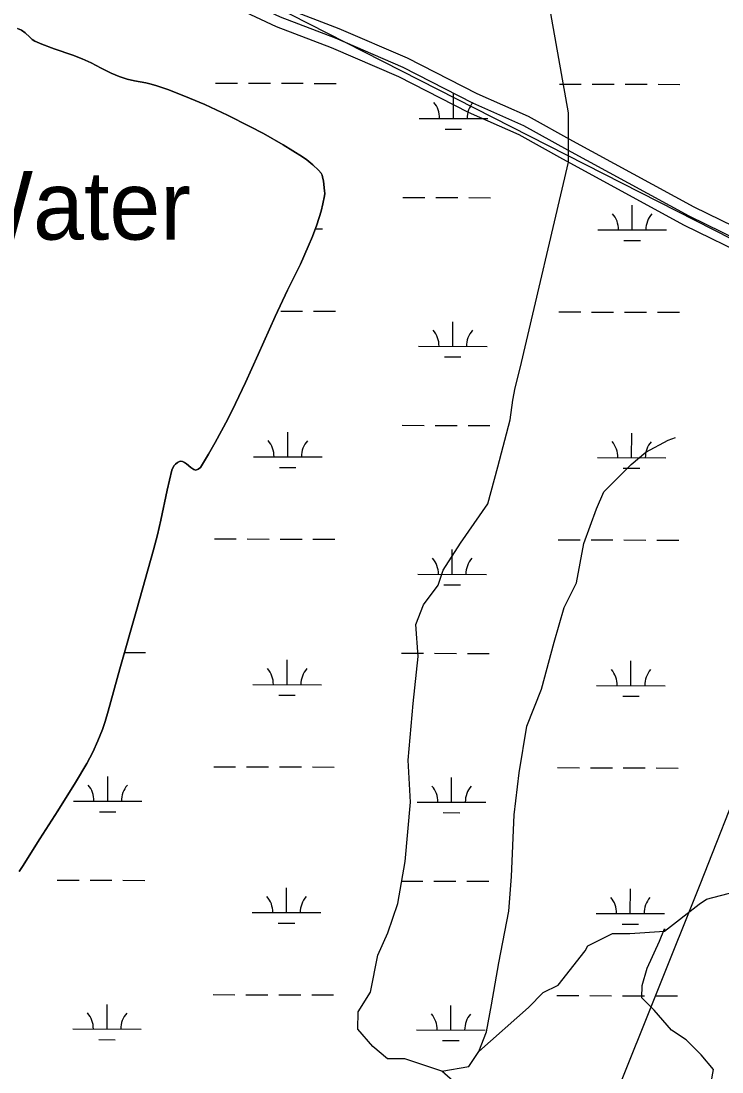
# Model space of a CAD drawing. Extents: x 3161615 to 3199515, y 867541 to 892976.
# Drawn here: x 3178916 to 3179939, y 876681 to 878215 of the extents above; entities that cross this region are included whole.
import ezdxf

# ---------------------------------------------------------------- set-up
doc = ezdxf.new("R2010")
doc.units = 0
for name, color, linetype in [('V-RIVR-IDEN', 7, 'Continuous'), ('V-ROAD-CNTR', 7, 'Continuous'), ('V-SITE-VEGE', 7, 'Continuous'), ('V-TOPO-BNDY', 7, 'Continuous'), ('V-TOPO-SHOR', 7, 'Continuous'), ('V-WETL-SWMP', 7, 'Continuous')]:
    doc.layers.add(name, color=color, linetype=linetype)

msp = doc.modelspace()

# ---------------------------------------------------------------- linework, layer by layer
at = {"layer": 'V-ROAD-CNTR'}
for points in [[(3180736.9, 877532.4), (3180600.2, 877601.6), (3180430.4, 877683.5), (3180339.3, 877732.1), (3180261.1, 877767.7), (3180178.8, 877806), (3180085.6, 877850.5), (3179995, 877895.6), (3179898, 877943.1), (3179721.1, 878039.2), (3179656.4, 878075.4), (3179581.6, 878108.4), (3179479.8, 878160.5), (3179380.1, 878203.6), (3179300.3, 878234), (3179180.9, 878290.4), (3179051.2, 878351.8), (3178954.2, 878389.2)], [(3180729.6, 877519.2), (3180593.6, 877588.2), (3180423.6, 877670.2), (3180332.7, 877718.6), (3180254.8, 877754.1), (3180172.4, 877792.4), (3180079.1, 877837), (3179988.4, 877882.2), (3179891.1, 877929.7), (3179713.9, 878026.1), (3179649.7, 878062), (3179575.1, 878094.9), (3179473.4, 878146.9), (3179374.5, 878189.7), (3179294.4, 878220.2), (3179174.5, 878276.9), (3179045.3, 878338), (3178948.8, 878375.2)], [(3180722.3, 877506.1), (3180587, 877574.7), (3180416.8, 877656.8), (3180326.1, 877705.2), (3180248.5, 877740.5), (3180166, 877778.8), (3180072.5, 877823.5), (3179981.7, 877868.7), (3179884.2, 877916.4), (3179706.6, 878012.9), (3179643, 878048.5), (3179568.7, 878081.4), (3179467, 878133.4), (3179368.8, 878175.8), (3179288.5, 878206.4), (3179168.1, 878263.3), (3179039.4, 878324.2), (3178943.4, 878361.2)]]:
    msp.add_lwpolyline(points, dxfattribs=at)
at = {"layer": 'V-SITE-VEGE'}
for p, q in [((3178910.6, 878203.8), (3178916.4, 878201.3)), ((3178916.4, 878201.3), (3178921.6, 878197.6)), ((3178921.6, 878197.6), (3178928.4, 878191)), ((3178928.4, 878191), (3178931.9, 878187.9)), ((3178931.9, 878187.9), (3178935.8, 878185.5)), ((3178935.8, 878185.5), (3178945.9, 878181.1)), ((3178945.9, 878181.1), (3178963.9, 878174.3)), ((3178963.9, 878174.3), (3178991.4, 878164.8)), ((3178991.4, 878164.8), (3179004.9, 878159.6)), ((3179004.9, 878159.6), (3179018.1, 878153.8)), ((3179018.1, 878153.8), (3179032.5, 878146.1)), ((3179032.5, 878146.1), (3179047.1, 878138.6)), ((3179047.1, 878138.6), (3179058.7, 878133.9)), ((3179058.7, 878133.9), (3179070.6, 878129.9)), ((3179070.6, 878129.9), (3179081.3, 878127.3)), ((3179081.3, 878127.3), (3179097.6, 878124.4)), ((3179097.6, 878124.4), (3179105.8, 878122.7)), ((3179105.8, 878122.7), (3179113.7, 878120.4)), ((3179113.7, 878120.4), (3179131.3, 878114.3)), ((3179131.3, 878114.3), (3179161.5, 878102.4)), ((3179161.5, 878102.4), (3179183.8, 878092.7)), ((3179183.8, 878092.7), (3179216.9, 878077.3)), ((3179216.9, 878077.3), (3179249.8, 878060.9)), ((3179249.8, 878060.9), (3179269.4, 878050.5)), ((3179269.4, 878050.5), (3179298.1, 878034.1)), ((3179298.1, 878034.1), (3179326.4, 878016.5)), ((3179326.4, 878016.5), (3179332.7, 878012.1)), ((3179332.7, 878012.1), (3179341.5, 878004.9)), ((3179341.5, 878004.9), (3179349.9, 877996.9)), ((3179349.9, 877996.9), (3179353.6, 877992.5)), ((3179353.6, 877992.5), (3179355, 877990)), ((3179355, 877990), (3179355.9, 877987.4)), ((3179355.9, 877987.4), (3179357.1, 877980.9)), ((3179357.1, 877980.9), (3179358.8, 877966.9)), ((3179358.8, 877966.9), (3179359, 877963.1)), ((3179358.7, 877959.4), (3179356.3, 877947.8)), ((3179359, 877963.1), (3179358.7, 877959.4)), ((3179353.6, 877937.1), (3179347.4, 877917.3)), ((3179356.3, 877947.8), (3179353.6, 877937.1)), ((3179347.4, 877917.3), (3179341.1, 877900.2)), ((3179341.1, 877900.2), (3179335, 877885.5)), ((3179335, 877885.5), (3179323.4, 877859.9)), ((3179323.4, 877859.9), (3179304.8, 877821.8)), ((3179304.8, 877821.8), (3179286.6, 877783.6)), ((3179286.6, 877783.6), (3179261.9, 877728.1)), ((3179261.9, 877728.1), (3179243.3, 877687)), ((3179243.3, 877687), (3179228.7, 877656.5)), ((3179228.7, 877656.5), (3179217.3, 877633.6)), ((3179217.3, 877633.6), (3179199.1, 877599.4)), ((3179199.1, 877599.4), (3179189.3, 877582.3)), ((3179189.3, 877582.3), (3179179.1, 877565.2)), ((3179139.2, 877565.8), (3179137.1, 877562.5)), ((3179141.1, 877567.9), (3179139.2, 877565.8)), ((3179143.8, 877570.1), (3179141.1, 877567.9)), ((3179146.8, 877571.6), (3179143.8, 877570.1)), ((3179148.8, 877572), (3179146.8, 877571.6)), ((3179151.2, 877571.9), (3179148.8, 877572)), ((3179154.4, 877570.5), (3179151.2, 877571.9)), ((3179157.4, 877568.3), (3179154.4, 877570.5)), ((3179163.5, 877563), (3179157.4, 877568.3)), ((3179179.1, 877565.2), (3179177.5, 877563.1)), ((3179135.7, 877558.9), (3179128.8, 877529.9)), ((3179137.1, 877562.5), (3179135.7, 877558.9)), ((3179167.8, 877560.1), (3179163.5, 877563)), ((3179169.3, 877559.4), (3179167.8, 877560.1)), ((3179170.9, 877559.2), (3179169.3, 877559.4)), ((3179174.4, 877560.5), (3179170.9, 877559.2)), ((3179177.5, 877563.1), (3179174.4, 877560.5)), ((3179128.8, 877529.9), (3179119.5, 877486.3)), ((3179119.5, 877486.3), (3179114.7, 877464.6)), ((3179114.7, 877464.6), (3179109.1, 877443)), ((3179109.1, 877443), (3179084.7, 877356)), ((3179084.7, 877356), (3179059.7, 877269)), ((3179059.7, 877269), (3179042.8, 877207.3)), ((3179042.8, 877207.3), (3179038.2, 877192)), ((3179038.2, 877192), (3179034.4, 877180.7)), ((3179034.4, 877180.7), (3179027.9, 877163.9)), ((3179027.9, 877163.9), (3179020.3, 877147.5)), ((3179020.3, 877147.5), (3179011.6, 877131.1)), ((3179011.6, 877131.1), (3178995.3, 877103)), ((3178995.3, 877103), (3178969.5, 877061.8)), ((3178969.5, 877061.8), (3178943.3, 877020.9)), ((3178943.3, 877020.9), (3178917.7, 876980.6)), ((3178917.7, 876980.6), (3178912.8, 876973.1))]:
    msp.add_line(p, q, dxfattribs=at)
at = {"layer": 'V-TOPO-BNDY'}
for p, q in [((3179906.8, 876954.4), (3180242.1, 877807.1)), ((3179703.3, 876445.8), (3179906.8, 876954.4))]:
    msp.add_line(p, q, dxfattribs=at)
at = {"layer": 'V-TOPO-SHOR'}
for points in [[(3179644.4, 877708.2), (3179714.6, 878008.9), (3179714.8, 878081), (3179686.4, 878239.6), (3179701, 878297.2), (3179672.3, 878369.4), (3179614.9, 878441.6), (3179542.9, 878470.7), (3179456.3, 878442.1), (3179355.4, 878413.5), (3179211.1, 878385.1), (3179110.3, 878399.8), (3179009.4, 878400.1), (3178908.5, 878429.2), (3178793.5, 878516), (3178750.3, 878530.5)], [(3178932.8, 878416.5), (3180491, 877623), (3180753.7, 877499.7)], [(3179004.9, 878159.6), (3178991.4, 878164.8), (3178963.9, 878174.3), (3178945.9, 878181.1), (3178935.8, 878185.5), (3178931.9, 878187.9), (3178928.4, 878191), (3178921.6, 878197.6), (3178916.4, 878201.3), (3178910.6, 878203.8)], [(3178912.8, 876973.1), (3178917.7, 876980.6), (3178943.3, 877020.9), (3178969.5, 877061.8), (3178995.3, 877103), (3179011.6, 877131.1), (3179020.3, 877147.5), (3179027.9, 877163.9), (3179034.4, 877180.7), (3179038.2, 877192), (3179042.8, 877207.3), (3179059.7, 877269), (3179084.7, 877356), (3179109.1, 877443), (3179114.7, 877464.6), (3179119.5, 877486.3), (3179128.8, 877529.9), (3179135.7, 877558.9), (3179137.1, 877562.5), (3179139.2, 877565.8), (3179141.1, 877567.9), (3179143.8, 877570.1), (3179146.8, 877571.6), (3179148.8, 877572), (3179151.2, 877571.9), (3179154.4, 877570.5), (3179157.4, 877568.3), (3179163.5, 877563), (3179167.8, 877560.1), (3179169.3, 877559.4), (3179170.9, 877559.2), (3179174.4, 877560.5), (3179177.5, 877563.1), (3179179.1, 877565.2), (3179189.3, 877582.3), (3179199.1, 877599.4), (3179217.3, 877633.6), (3179228.7, 877656.5), (3179243.3, 877687), (3179261.9, 877728.1), (3179286.6, 877783.6), (3179304.8, 877821.8), (3179323.4, 877859.9), (3179335, 877885.5), (3179341.1, 877900.2), (3179347.4, 877917.3), (3179353.6, 877937.1), (3179356.3, 877947.8), (3179358.7, 877959.4), (3179359, 877963.1), (3179358.8, 877966.9), (3179357.1, 877980.9), (3179355.9, 877987.4), (3179355, 877990), (3179353.6, 877992.5), (3179349.9, 877996.9), (3179341.5, 878004.9), (3179332.7, 878012.1), (3179326.4, 878016.5), (3179298.1, 878034.1), (3179269.4, 878050.5), (3179249.8, 878060.9), (3179216.9, 878077.3), (3179183.8, 878092.7), (3179161.5, 878102.4), (3179131.3, 878114.3), (3179113.7, 878120.4), (3179105.8, 878122.7), (3179097.6, 878124.4), (3179081.3, 878127.3), (3179070.6, 878129.9), (3179058.7, 878133.9), (3179047.1, 878138.6), (3179032.5, 878146.1), (3179018.1, 878153.8), (3179004.9, 878159.6)], [(3179558.6, 876656.2), (3179529.8, 876681.5), (3179475.8, 876699.6), (3179450.6, 876699.7), (3179429, 876717.8), (3179407.5, 876743.1), (3179407.6, 876768.3), (3179425.7, 876797.1), (3179436.6, 876851.1), (3179451.1, 876883.5), (3179465.7, 876926.7), (3179476.6, 876987.9), (3179484.1, 877074.4), (3179480.6, 877135.7), (3179488.1, 877218.5), (3179495.5, 877287), (3179492, 877333.8), (3179502.9, 877362.6), (3179524.6, 877391.4), (3179531.9, 877413), (3179557.2, 877452.6), (3179597, 877510.1), (3179611.6, 877564.1), (3179629.8, 877632.6), (3179633.5, 877661.4), (3179637.1, 877679.4), (3179644.4, 877708.2)], [(3179529.8, 876681.5), (3179569.5, 876688.6), (3179584, 876710.2), (3179594.9, 876739), (3179602.2, 876778.6), (3179613.2, 876839.8), (3179627.8, 876915.4), (3179631.5, 876965.9), (3179635.4, 877056), (3179642.8, 877117.2), (3179653.8, 877185.6), (3179675.5, 877239.6), (3179693.7, 877308.1), (3179708.3, 877358.5), (3179726.4, 877394.5), (3179737.4, 877452.1), (3179755.5, 877502.5), (3179766.4, 877527.7), (3179806.2, 877567.2), (3179827.8, 877585.2), (3179860.3, 877603.1), (3179871.1, 877606.7)], [(3179584, 876710.2), (3179656.2, 876774.8), (3179677.9, 876796.4), (3179699.6, 876807.1), (3179739.3, 876857.5), (3179743, 876864.7), (3179779.1, 876882.6), (3179804.3, 876882.5), (3179854.7, 876886), (3179905.3, 876925.5), (3179916.1, 876932.7), (3180024.3, 876961.2)], [(3179918.9, 876640.8), (3179926.3, 876684), (3179908.3, 876705.7), (3179886.7, 876727.3), (3179865.2, 876741.8), (3179840, 876770.7), (3179822, 876788.8), (3179822.1, 876806.8), (3179829.4, 876832), (3179847.5, 876871.6), (3179854.7, 876889.6), (3179854.7, 876886)]]:
    msp.add_lwpolyline(points, dxfattribs=at)
at = {"layer": 'V-WETL-SWMP'}
for p, q in [((3178916.4, 878201.3), (3178910.6, 878203.8)), ((3178921.6, 878197.6), (3178916.4, 878201.3)), ((3178928.4, 878191), (3178921.6, 878197.6)), ((3178931.9, 878187.9), (3178928.4, 878191)), ((3178935.8, 878185.5), (3178931.9, 878187.9)), ((3178945.9, 878181.1), (3178935.8, 878185.5)), ((3178963.9, 878174.3), (3178945.9, 878181.1)), ((3178991.4, 878164.8), (3178963.9, 878174.3)), ((3179004.9, 878159.6), (3178991.4, 878164.8)), ((3179018.1, 878153.8), (3179004.9, 878159.6)), ((3179032.5, 878146.1), (3179018.1, 878153.8)), ((3179047.1, 878138.6), (3179032.5, 878146.1)), ((3179058.7, 878133.9), (3179047.1, 878138.6)), ((3179070.6, 878129.9), (3179058.7, 878133.9)), ((3179081.3, 878127.3), (3179070.6, 878129.9)), ((3179097.6, 878124.4), (3179081.3, 878127.3)), ((3179105.8, 878122.7), (3179097.6, 878124.4)), ((3179113.7, 878120.4), (3179105.8, 878122.7)), ((3179131.3, 878114.3), (3179113.7, 878120.4)), ((3179199.6, 878124.2), (3179231.6, 878124.1)), ((3179247.6, 878124.1), (3179279.6, 878124)), ((3179295.6, 878123.9), (3179327.6, 878123.9)), ((3179343.6, 878123.8), (3179375.6, 878123.7)), ((3179701.5, 878122.8), (3179733.5, 878122.7)), ((3179749.5, 878122.7), (3179781.5, 878122.6)), ((3179797.5, 878122.6), (3179829.5, 878122.5)), ((3179845.5, 878122.4), (3179877.5, 878122.3)), ((3179161.5, 878102.4), (3179131.3, 878114.3)), ((3179183.8, 878092.7), (3179161.5, 878102.4)), ((3179546.8, 878072.5), (3179546.9, 878108.5)), ((3179216.9, 878077.3), (3179183.8, 878092.7)), ((3179249.8, 878060.9), (3179216.9, 878077.3)), ((3179496.8, 878072.7), (3179596.8, 878072.4)), ((3179269.4, 878050.5), (3179249.8, 878060.9)), ((3179534.7, 878057.1), (3179558.7, 878057)), ((3179298.1, 878034.1), (3179269.4, 878050.5)), ((3179326.4, 878016.5), (3179298.1, 878034.1)), ((3179332.7, 878012.1), (3179326.4, 878016.5)), ((3179341.5, 878004.9), (3179332.7, 878012.1)), ((3179349.9, 877996.9), (3179341.5, 878004.9)), ((3179353.6, 877992.5), (3179349.9, 877996.9)), ((3179355, 877990), (3179353.6, 877992.5)), ((3179355.9, 877987.4), (3179355, 877990)), ((3179357.1, 877980.9), (3179355.9, 877987.4)), ((3179358.8, 877966.9), (3179357.1, 877980.9)), ((3179359, 877963.1), (3179358.8, 877966.9)), ((3179356.3, 877947.8), (3179358.7, 877959.4)), ((3179358.7, 877959.4), (3179359, 877963.1)), ((3179473.1, 877957.3), (3179505.1, 877957.2)), ((3179521.1, 877957.2), (3179553.1, 877957.1)), ((3179569.1, 877957), (3179601.1, 877956.9)), ((3179347.4, 877917.3), (3179353.6, 877937.1)), ((3179353.6, 877937.1), (3179356.3, 877947.8)), ((3179807.8, 877909.9), (3179807.9, 877945.9)), ((3179341.1, 877900.2), (3179347.4, 877917.3)), ((3179345.2, 877911.2), (3179355.9, 877911.2)), ((3179757.8, 877910.1), (3179857.8, 877909.8)), ((3179335, 877885.5), (3179341.1, 877900.2)), ((3179795.7, 877894.5), (3179819.7, 877894.5)), ((3179323.4, 877859.9), (3179335, 877885.5)), ((3179304.8, 877821.8), (3179323.4, 877859.9)), ((3179286.6, 877783.6), (3179304.8, 877821.8)), ((3179261.9, 877728.1), (3179286.6, 877783.6)), ((3179294.7, 877791.3), (3179326.7, 877791.2)), ((3179342.7, 877791.1), (3179374.7, 877791.1)), ((3179700.6, 877790.2), (3179732.6, 877790.1)), ((3179748.6, 877790), (3179780.6, 877789.9)), ((3179796.6, 877789.9), (3179828.6, 877789.8)), ((3179844.6, 877789.8), (3179876.6, 877789.7)), ((3179545.9, 877739.8), (3179546, 877775.8)), ((3179495.9, 877740), (3179595.9, 877739.7)), ((3179243.3, 877687), (3179261.9, 877728.1)), ((3179533.8, 877724.4), (3179557.8, 877724.4)), ((3179228.7, 877656.5), (3179243.3, 877687)), ((3179217.3, 877633.6), (3179228.7, 877656.5)), ((3179199.1, 877599.4), (3179217.3, 877633.6)), ((3179305, 877578.6), (3179305.1, 877614.6)), ((3179472.1, 877624.6), (3179504.1, 877624.5)), ((3179520.1, 877624.5), (3179552.1, 877624.4)), ((3179568.1, 877624.3), (3179600.1, 877624.3)), ((3179806.9, 877577.3), (3179807, 877613.3)), ((3179189.3, 877582.3), (3179199.1, 877599.4)), ((3179179.1, 877565.2), (3179189.3, 877582.3)), ((3179137.1, 877562.5), (3179139.2, 877565.8)), ((3179139.2, 877565.8), (3179141.1, 877567.9)), ((3179141.1, 877567.9), (3179143.8, 877570.1)), ((3179143.8, 877570.1), (3179146.8, 877571.6)), ((3179146.8, 877571.6), (3179148.8, 877572)), ((3179148.8, 877572), (3179151.2, 877571.9)), ((3179151.2, 877571.9), (3179154.4, 877570.5)), ((3179154.4, 877570.5), (3179157.4, 877568.3)), ((3179157.4, 877568.3), (3179163.5, 877563)), ((3179177.5, 877563.1), (3179179.1, 877565.2)), ((3179255, 877578.8), (3179355, 877578.5)), ((3179756.9, 877577.4), (3179856.9, 877577.1)), ((3179128.8, 877529.9), (3179135.7, 877558.9)), ((3179135.7, 877558.9), (3179137.1, 877562.5)), ((3179163.5, 877563), (3179167.8, 877560.1)), ((3179167.8, 877560.1), (3179169.3, 877559.4)), ((3179169.3, 877559.4), (3179170.9, 877559.2)), ((3179170.9, 877559.2), (3179174.4, 877560.5)), ((3179174.4, 877560.5), (3179177.5, 877563.1)), ((3179292.9, 877563.2), (3179316.9, 877563.2)), ((3179794.8, 877561.9), (3179818.8, 877561.8)), ((3179119.5, 877486.3), (3179128.8, 877529.9)), ((3179114.7, 877464.6), (3179119.5, 877486.3)), ((3179109.1, 877443), (3179114.7, 877464.6)), ((3179197.8, 877458.9), (3179229.8, 877458.8)), ((3179245.8, 877458.7), (3179277.8, 877458.6)), ((3179293.8, 877458.6), (3179325.8, 877458.5)), ((3179341.8, 877458.5), (3179373.8, 877458.4)), ((3179699.7, 877457.5), (3179731.7, 877457.4)), ((3179747.7, 877457.3), (3179779.7, 877457.3)), ((3179795.7, 877457.2), (3179827.7, 877457.1)), ((3179843.7, 877457.1), (3179875.7, 877457)), ((3179084.7, 877356), (3179109.1, 877443)), ((3179545, 877407.2), (3179545.1, 877443.2)), ((3179495, 877407.3), (3179595, 877407)), ((3179532.9, 877391.8), (3179556.9, 877391.7)), ((3179059.7, 877269), (3179084.7, 877356)), ((3179066.6, 877293.1), (3179097.3, 877293)), ((3179471.2, 877291.9), (3179503.2, 877291.8)), ((3179519.2, 877291.8), (3179551.2, 877291.7)), ((3179567.2, 877291.7), (3179599.2, 877291.6)), ((3179304, 877246), (3179304.1, 877282)), ((3179805.9, 877244.6), (3179806, 877280.6)), ((3179042.8, 877207.3), (3179059.7, 877269)), ((3179254, 877246.1), (3179354, 877245.8)), ((3179755.9, 877244.7), (3179855.9, 877244.4)), ((3179292, 877230.6), (3179316, 877230.5)), ((3179793.9, 877229.2), (3179817.9, 877229.1)), ((3179038.2, 877192), (3179042.8, 877207.3)), ((3179034.4, 877180.7), (3179038.2, 877192)), ((3179027.9, 877163.9), (3179034.4, 877180.7)), ((3179020.3, 877147.5), (3179027.9, 877163.9)), ((3179011.6, 877131.1), (3179020.3, 877147.5)), ((3178995.3, 877103), (3179011.6, 877131.1)), ((3179196.9, 877126.2), (3179228.9, 877126.1)), ((3179244.9, 877126.1), (3179276.9, 877126)), ((3179292.9, 877125.9), (3179324.9, 877125.8)), ((3179340.9, 877125.8), (3179372.9, 877125.7)), ((3179698.8, 877124.8), (3179730.8, 877124.7)), ((3179746.8, 877124.7), (3179778.8, 877124.6)), ((3179794.8, 877124.5), (3179826.8, 877124.5)), ((3179842.8, 877124.4), (3179874.8, 877124.3)), ((3179042.1, 877075.9), (3179042.2, 877111.9)), ((3179544, 877074.5), (3179544.1, 877110.5)), ((3178969.5, 877061.8), (3178995.3, 877103)), ((3178992.1, 877076), (3179092.1, 877075.7)), ((3179494, 877074.6), (3179594, 877074.4)), ((3178943.3, 877020.9), (3178969.5, 877061.8)), ((3179030.1, 877060.5), (3179054.1, 877060.4)), ((3179532, 877059.1), (3179556, 877059)), ((3178917.7, 876980.6), (3178943.3, 877020.9)), ((3178912.8, 876973.1), (3178917.7, 876980.6)), ((3178968.4, 876960.6), (3179000.4, 876960.6)), ((3179016.4, 876960.5), (3179048.4, 876960.4)), ((3179064.4, 876960.4), (3179096.4, 876960.3)), ((3179470.3, 876959.3), (3179502.3, 876959.2)), ((3179518.3, 876959.1), (3179550.3, 876959)), ((3179566.3, 876959), (3179598.3, 876958.9)), ((3179303.1, 876913.3), (3179303.2, 876949.3)), ((3179805, 876911.9), (3179805.1, 876947.9)), ((3179253.1, 876913.4), (3179353.1, 876913.2)), ((3179755, 876912), (3179855, 876911.8)), ((3179291.1, 876897.9), (3179315.1, 876897.8)), ((3179793, 876896.5), (3179817, 876896.4)), ((3179195.9, 876793.5), (3179227.9, 876793.4)), ((3179243.9, 876793.4), (3179275.9, 876793.3)), ((3179291.9, 876793.3), (3179323.9, 876793.2)), ((3179339.9, 876793.1), (3179371.9, 876793)), ((3179697.8, 876792.1), (3179729.8, 876792)), ((3179745.8, 876792), (3179777.8, 876791.9)), ((3179793.8, 876791.9), (3179825.8, 876791.8)), ((3179841.8, 876791.7), (3179873.8, 876791.6)), ((3179041.2, 876743.2), (3179041.3, 876779.2)), ((3179543.1, 876741.8), (3179543.2, 876777.8)), ((3178991.2, 876743.3), (3179091.2, 876743.1)), ((3179493.1, 876742), (3179593.1, 876741.7)), ((3179029.2, 876727.8), (3179053.2, 876727.7)), ((3179531.1, 876726.4), (3179555.1, 876726.4))]:
    msp.add_line(p, q, dxfattribs=at)
for centre, start, end in [((3179491.5, 878073.1), 359.0699, 40.6135), ((3179602, 878072.8), 139.0699, 180.6135), ((3179752.5, 877910.6), 359.0699, 40.6135), ((3179863, 877910.3), 139.0699, 180.6135), ((3179490.6, 877740.5), 359.0699, 40.6135), ((3179601.1, 877740.2), 139.0699, 180.6135), ((3179249.7, 877579.3), 359.0699, 40.6135), ((3179360.2, 877579), 139.0699, 180.6135), ((3179751.6, 877577.9), 359.0699, 40.6135), ((3179862.1, 877577.6), 139.0699, 180.6135), ((3179489.7, 877407.8), 359.0699, 40.6135), ((3179600.2, 877407.5), 139.0699, 180.6135), ((3179248.8, 877246.6), 359.0699, 40.6135), ((3179359.3, 877246.3), 139.0699, 180.6135), ((3179750.7, 877245.2), 359.0699, 40.6135), ((3179861.2, 877244.9), 139.0699, 180.6135), ((3178986.9, 877076.5), 359.0699, 40.6135), ((3179097.4, 877076.2), 139.0699, 180.6135), ((3179488.8, 877075.1), 359.0699, 40.6135), ((3179599.3, 877074.8), 139.0699, 180.6135), ((3179247.9, 876913.9), 359.0699, 40.6135), ((3179358.4, 876913.6), 139.0699, 180.6135), ((3179749.8, 876912.5), 359.0699, 40.6135), ((3179860.3, 876912.2), 139.0699, 180.6135), ((3178986, 876743.8), 359.0699, 40.6135), ((3179096.5, 876743.5), 139.0699, 180.6135), ((3179487.9, 876742.4), 359.0699, 40.6135), ((3179598.4, 876742.1), 139.0699, 180.6135)]:
    msp.add_arc(centre, 35.2, start, end, dxfattribs=at)

# ---------------------------------------------------------------- texts
at = {"layer": 'V-RIVR-IDEN'}
msp.add_text('Water', height=100, dxfattribs=at).set_placement((3178806.8, 877895.7))

doc.saveas('drawing.dxf')
